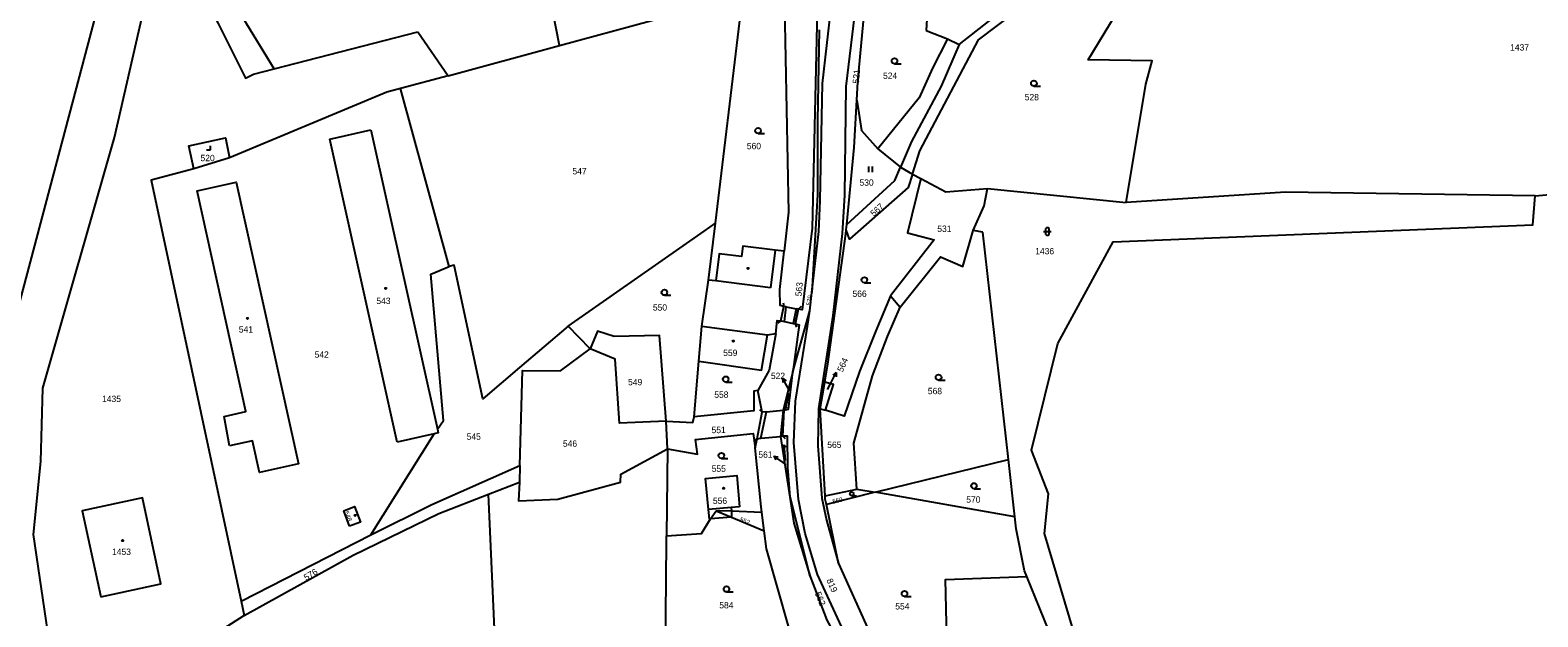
# Model space of a CAD drawing. Extents: x -520431 to -517205, y -1075927 to -1074013.
# Drawn here: x -518119.2 to -517715.9, y -1075681.5 to -1075524.8 of the extents above; entities that cross this region are included whole.
import ezdxf

# ---------------------------------------------------------------- set-up
doc = ezdxf.new("R2010")
doc.units = 0
for name, color, linetype in [('Hranice parcel', 7, 'Continuous'), ('Parcelní čísla', 7, 'Continuous'), ('Pop  PČ popisy', 7, 'Continuous'), ('Vnitřní kresba', 7, 'Continuous'), ('Značky budov', 7, 'Continuous'), ('Značky kultur', 7, 'Continuous')]:
    doc.layers.add(name, color=color, linetype=linetype)

msp = doc.modelspace()

# ---------------------------------------------------------------- linework, layer by layer
at = {"layer": 'Hranice parcel'}
for p, q in [((-517870.65, -1075528.6), (-517828.64, -1075495.46)), ((-517877.8, -1075495.74), (-517879.5, -1075524.81)), ((-517977.61, -1075528.88), (-517983.14, -1075499.93)), ((-517897.78, -1075538.57), (-517895.15, -1075510.36)), ((-517977.61, -1075528.88), (-517928.42, -1075515.49)), ((-518053.92, -1075535.11), (-518062.2, -1075521.51)), ((-517935.86, -1075576.31), (-517929.37, -1075522.17)), ((-518053.92, -1075535.11), (-518015.43, -1075525.22)), ((-518015.43, -1075525.22), (-518007.35, -1075536.98)), ((-517879.5, -1075524.81), (-517873.81, -1075527.06)), ((-517873.81, -1075527.06), (-517870.65, -1075528.6)), ((-518007.35, -1075536.98), (-517977.61, -1075528.88)), ((-518059.46, -1075536.53), (-518053.92, -1075535.11)), ((-518007.35, -1075536.98), (-518020.07, -1075540.33)), ((-517898.04, -1075543.43), (-517897.78, -1075538.57)), ((-518023.78, -1075541.31), (-518065.82, -1075558.88)), ((-518020.07, -1075540.33), (-518023.78, -1075541.31)), ((-518007.12, -1075587.89), (-518020.07, -1075540.33)), ((-518028.03, -1075551.41), (-518010.22, -1075631.43)), ((-518065.82, -1075558.88), (-518075.42, -1075561.82)), ((-517886.37, -1075561.4), (-517883.1, -1075563.22)), ((-517883.1, -1075563.22), (-517880.95, -1075564.42)), ((-517863.05, -1075567.09), (-517826.01, -1075570.84)), ((-517937.69, -1075591.53), (-517935.86, -1075576.31)), ((-517910.03, -1075594.89), (-517908.23, -1075578.54)), ((-517905.82, -1075614.05), (-517900.96, -1075579.19)), ((-517900.96, -1075579.19), (-517900.86, -1075578.16)), ((-517900.86, -1075578.16), (-517900.72, -1075576.71)), ((-517864.36, -1075578.76), (-517866.89, -1075578.28)), ((-517857.49, -1075639.51), (-517864.36, -1075578.76)), ((-517910.57, -1075599.74), (-517910.03, -1075594.89)), ((-517889.02, -1075595.73), (-517886.44, -1075598.8)), ((-517916.95, -1075598.69), (-517917.55, -1075598.58)), ((-517917.39, -1075602.63), (-517916.95, -1075598.69)), ((-517915.13, -1075616.09), (-517910.57, -1075599.74)), ((-517914.28, -1075599.21), (-517915.06, -1075603.11)), ((-517913.64, -1075599.33), (-517914.28, -1075599.21)), ((-517969.34, -1075609.95), (-517975.23, -1075603.83)), ((-517918.34, -1075602.44), (-517917.39, -1075602.63)), ((-517915.06, -1075603.11), (-517914.42, -1075603.24)), ((-517941.52, -1075628.09), (-517940.29, -1075613.25)), ((-517915.13, -1075616.09), (-517917.75, -1075626.3)), ((-517906.62, -1075618.8), (-517905.82, -1075614.05)), ((-517907.84, -1075625.92), (-517906.62, -1075618.8)), ((-517923.35, -1075626.86), (-517924.48, -1075621.04)), ((-517923.75, -1075633.75), (-517922.2, -1075626.75)), ((-517922.2, -1075626.75), (-517923.35, -1075626.86)), ((-517917.75, -1075626.3), (-517918.44, -1075633.31)), ((-517917.75, -1075626.3), (-517917.44, -1075626.27)), ((-517907.84, -1075625.92), (-517906.46, -1075626.34)), ((-517906.52, -1075649.19), (-517907.84, -1075625.92)), ((-518028.08, -1075659.64), (-518011.08, -1075632.65)), ((-518011.08, -1075632.65), (-518021.04, -1075634.9)), ((-517948.68, -1075636.65), (-517949.07, -1075629.21)), ((-517948.68, -1075636.65), (-517948.92, -1075659.87)), ((-517923.67, -1075652.14), (-517925.21, -1075636.42)), ((-517923.75, -1075633.75), (-517918.44, -1075633.31)), ((-517917.8, -1075633.25), (-517918.44, -1075633.31)), ((-517893.09, -1075648.23), (-517857.49, -1075639.51)), ((-517855.75, -1075654.84), (-517857.49, -1075639.51)), ((-517988.19, -1075641.07), (-517988.31, -1075645.53)), ((-517996.53, -1075648.79), (-517988.31, -1075645.53)), ((-517993.21, -1075725.03), (-517996.53, -1075648.79)), ((-517906.52, -1075649.19), (-517898.04, -1075647.38)), ((-517893.09, -1075648.23), (-517906.17, -1075651.54)), ((-517898.04, -1075647.38), (-517893.09, -1075648.23)), ((-517855.75, -1075654.84), (-517893.09, -1075648.23)), ((-517923.48, -1075653.64), (-517923.67, -1075652.14)), ((-517902.93, -1075667.29), (-517906.17, -1075651.54)), ((-517922.85, -1075658.53), (-517923.48, -1075653.64)), ((-517855.39, -1075658.03), (-517855.75, -1075654.84)), ((-518062.74, -1075677.38), (-518028.08, -1075659.64)), ((-517948.93, -1075661.56), (-517948.92, -1075659.87)), ((-517922.24, -1075663.35), (-517922.85, -1075658.53)), ((-517853.17, -1075669.24), (-517855.39, -1075658.03)), ((-517949.22, -1075695.82), (-517948.93, -1075661.56)), ((-517852.53, -1075670.8), (-517853.17, -1075669.24)), ((-517841.94, -1075696.76), (-517852.53, -1075670.8)), ((-518062.74, -1075677.38), (-518061.96, -1075681.23))]:
    msp.add_line(p, q, dxfattribs=at)
for points in [[(-517908.23, -1075578.54), (-517907.82, -1075570.25), (-517907.25, -1075539.04), (-517904.89, -1075518.73), (-517894.6, -1075467.56), (-517894.25, -1075463.86), (-517894.26, -1075460.26), (-517894.52, -1075452.87), (-517896.56, -1075433.9), (-517897.16, -1075426.01)], [(-517887.9, -1075457.19), (-517887.87, -1075460.35), (-517887.85, -1075462.57), (-517888.37, -1075468.59), (-517898.63, -1075520.7), (-517900.94, -1075539.84), (-517901.33, -1075568.86), (-517901.96, -1075579.13), (-517904.42, -1075601.03), (-517908.33, -1075625.84), (-517908.44, -1075635.83), (-517907.36, -1075649.79), (-517906.18, -1075655.68), (-517902.93, -1075667.29)], [(-518107.27, -1075709.57), (-518109.82, -1075693.22), (-518114.05, -1075688.54), (-518118.33, -1075659.57), (-518116.37, -1075640), (-518115.8, -1075620.46), (-518096.66, -1075553.44), (-518083.3, -1075495.38)], [(-518083.3, -1075495.38), (-518068.88, -1075522.94), (-518061.62, -1075537.56), (-518059.46, -1075536.53)], [(-517883.1, -1075563.22), (-517881.14, -1075557.03), (-517865.49, -1075527.34), (-517830.65, -1075500.93), (-517817.63, -1075493.15)], [(-518125.69, -1075721.88), (-518120.86, -1075706.74), (-518130.94, -1075649.23), (-518129.54, -1075625.65), (-518098.36, -1075508.57)], [(-517826.01, -1075570.84), (-517820.72, -1075539.22), (-517819, -1075532.99), (-517836.13, -1075532.69), (-517828.86, -1075520.67), (-517825.45, -1075508.41)], [(-517908.58, -1075515.54), (-517909.96, -1075577.65), (-517912.64, -1075599.49), (-517913.64, -1075599.33)], [(-517917.41, -1075518.48), (-517916.31, -1075573.36), (-517917.48, -1075583.83)], [(-517908.1, -1075524.7), (-517908.53, -1075549.01), (-517908.55, -1075568.78), (-517910.03, -1075594.89)], [(-517870.65, -1075528.6), (-517875.48, -1075539.71), (-517883.4, -1075554.48), (-517886.37, -1075561.4)], [(-517716.55, -1075569.07), (-517630.97, -1075561.31), (-517618.08, -1075550.38), (-517597.53, -1075535.05)], [(-517900.72, -1075576.71), (-517898.72, -1075556.11), (-517898.04, -1075543.43)], [(-517898.04, -1075543.43), (-517896.75, -1075551.54), (-517892.38, -1075556.45), (-517886.37, -1075561.4)], [(-518021.04, -1075634.9), (-518039.06, -1075553.91), (-518028.03, -1075551.41)], [(-518075.42, -1075561.82), (-518076.74, -1075555.66), (-518066.97, -1075553.51), (-518065.82, -1075558.88)], [(-518075.42, -1075561.82), (-518086.84, -1075564.87), (-518062.74, -1075677.38)], [(-517883.1, -1075563.22), (-517884.26, -1075566.8), (-517900.01, -1075580.61), (-517900.86, -1075578.16)], [(-517900.72, -1075576.71), (-517887.91, -1075564.97), (-517886.37, -1075561.4)], [(-518065.82, -1075635.81), (-518067.3, -1075627.99), (-518061.45, -1075626.7), (-518074.47, -1075567.68), (-518064.06, -1075565.34), (-518047.38, -1075640.64), (-518057.86, -1075642.96), (-518059.73, -1075634.47), (-518065.82, -1075635.81)], [(-517880.95, -1075564.42), (-517884.46, -1075578.96), (-517877.31, -1075580.76), (-517889.02, -1075595.73)], [(-517880.95, -1075564.42), (-517874.26, -1075567.99), (-517863.05, -1075567.09)], [(-517866.89, -1075578.28), (-517863.94, -1075571.66), (-517863.05, -1075567.09)], [(-517716.55, -1075569.07), (-517783.34, -1075568.02), (-517826.01, -1075570.84)], [(-517806.36, -1075723.7), (-517819.22, -1075715.13), (-517837.94, -1075692.54), (-517847.81, -1075659.24), (-517846.75, -1075648.71), (-517851.31, -1075636.96), (-517844.3, -1075608.48), (-517829.48, -1075581.32), (-517717.18, -1075576.77), (-517716.55, -1075569.07)], [(-517975.23, -1075603.83), (-517938.87, -1075578.49), (-517935.86, -1075576.31)], [(-517886.44, -1075598.8), (-517875.65, -1075585.3), (-517869.71, -1075587.89), (-517866.89, -1075578.28)], [(-517917.48, -1075583.83), (-517919.87, -1075583.54), (-517928.54, -1075582.47), (-517928.89, -1075585.27), (-517934.9, -1075584.54), (-517935.78, -1075591.76), (-517937.69, -1075591.53)], [(-517917.55, -1075598.58), (-517918.58, -1075598.32), (-517918.63, -1075594.02), (-517917.48, -1075583.83)], [(-518010.22, -1075631.43), (-518008.61, -1075629.06), (-518012.03, -1075589.98), (-518007.12, -1075587.89)], [(-517975.23, -1075603.83), (-517988.3, -1075614.95), (-517998.11, -1075623.27), (-518005.74, -1075587.57), (-518007.12, -1075587.89)], [(-517940.29, -1075613.25), (-517939.49, -1075603.84), (-517937.69, -1075591.53)], [(-517889.02, -1075595.73), (-517892.94, -1075605.07), (-517897.34, -1075616.02), (-517901.44, -1075627.88), (-517906.46, -1075626.34)], [(-517893.06, -1075703.93), (-517895.1, -1075699.24), (-517897.65, -1075693.7), (-517900.03, -1075688.77), (-517908.54, -1075670.21), (-517911.85, -1075659.26), (-517913.67, -1075650.22), (-517914.9, -1075634.97), (-517914.4, -1075623.91), (-517911.26, -1075603.96), (-517910.57, -1075599.74)], [(-517898.04, -1075647.38), (-517898.86, -1075635.1), (-517893.86, -1075617.11), (-517889.87, -1075606.66), (-517886.44, -1075598.8)], [(-517919.71, -1075605.79), (-517919.38, -1075602.32), (-517918.34, -1075602.44)], [(-517914.42, -1075603.24), (-517913.48, -1075603.52), (-517915.13, -1075616.09)], [(-517949.07, -1075629.21), (-517950.86, -1075606.4), (-517962.96, -1075606.59), (-517967.43, -1075605.2), (-517969.34, -1075609.95)], [(-517940.29, -1075613.25), (-517923.51, -1075615.6), (-517921.97, -1075606.18), (-517919.71, -1075605.79)], [(-517919.71, -1075605.79), (-517921.51, -1075615.62), (-517924.48, -1075621.04)], [(-517988.19, -1075641.07), (-517987.5, -1075615.72), (-517977.28, -1075615.8), (-517969.34, -1075609.95)], [(-517949.07, -1075629.21), (-517961.56, -1075629.77), (-517962.69, -1075612.65), (-517969.34, -1075609.95)], [(-517917.44, -1075626.27), (-517916.3, -1075626.06), (-517915.13, -1075616.09)], [(-517906.46, -1075626.34), (-517904.25, -1075619.42), (-517906.62, -1075618.8)], [(-517924.48, -1075621.04), (-517925.56, -1075621.25), (-517925.56, -1075626.51), (-517941.52, -1075628.09)], [(-517949.07, -1075629.21), (-517941.95, -1075629.65), (-517941.52, -1075628.09)], [(-518010.22, -1075631.43), (-518010, -1075632.41), (-518011.08, -1075632.65)], [(-517948.68, -1075636.65), (-517940.66, -1075638.09), (-517941.16, -1075634.17), (-517925.81, -1075632.57), (-517925.21, -1075636.42)], [(-517988.31, -1075645.53), (-517988.57, -1075650.56), (-517978, -1075650.14), (-517961.23, -1075645.55), (-517961.2, -1075643.42), (-517948.68, -1075636.65)], [(-517925.21, -1075636.42), (-517924.74, -1075633.99), (-517923.75, -1075633.75)], [(-517918.44, -1075633.31), (-517914.87, -1075656.49), (-517910.5, -1075670.78)], [(-517910.5, -1075670.78), (-517915.9, -1075649.51), (-517916.49, -1075641.59), (-517916.6, -1075633.27), (-517917.8, -1075633.25)], [(-518028.08, -1075659.64), (-518011.75, -1075651.48), (-517988.19, -1075641.07)], [(-517929.44, -1075652.16), (-517931.65, -1075652.36), (-517937.7, -1075652.89), (-517938.52, -1075644.57), (-517930.18, -1075643.81), (-517929.44, -1075652.16)], [(-518061.96, -1075681.23), (-518032.8, -1075665.09), (-518009.83, -1075653.95), (-517996.53, -1075648.79)], [(-518100.32, -1075676.22), (-518084.2, -1075672.69), (-518089.16, -1075649.7), (-518105.3, -1075653.18), (-518100.32, -1075676.22)], [(-518033.78, -1075657.29), (-518035.28, -1075653.19), (-518032.38, -1075652.09), (-518030.85, -1075656.21), (-518033.78, -1075657.29)], [(-517906.17, -1075651.54), (-517906.47, -1075650.06), (-517906.52, -1075649.19)], [(-517948.92, -1075659.87), (-517939.59, -1075659.29), (-517937.16, -1075655.38), (-517935.65, -1075653.19)], [(-517935.65, -1075653.19), (-517931.53, -1075654.95), (-517922.85, -1075658.53)], [(-517923.48, -1075653.64), (-517931.6, -1075653.34), (-517935.65, -1075653.19)], [(-517915.44, -1075686.85), (-517916.32, -1075684.08), (-517922.24, -1075663.35)], [(-517902.93, -1075667.29), (-517894.81, -1075685.27), (-517889.37, -1075696.64), (-517884.79, -1075710.63)], [(-517910.5, -1075670.78), (-517906.1, -1075682.41), (-517902.27, -1075689.29)], [(-517863.8, -1075732.34), (-517873.73, -1075698.85), (-517874.32, -1075671.54), (-517852.53, -1075670.8)], [(-518061.96, -1075681.23), (-518069.84, -1075686.25), (-518090.4, -1075701.07), (-518099.28, -1075708.75), (-518088.14, -1075746.39)]]:
    msp.add_lwpolyline(points, dxfattribs=at)
at = {"layer": 'Pop  PČ popisy'}
for p, q in [((-517904.93, -1075618.95), (-517903.57, -1075616.28)), ((-517903.57, -1075616.28), (-517904.47, -1075616.94)), ((-517903.57, -1075616.28), (-517903.58, -1075617.4)), ((-517916.42, -1075620.42), (-517917.88, -1075617.79)), ((-517917.88, -1075617.79), (-517916.95, -1075618.43)), ((-517917.88, -1075617.79), (-517917.83, -1075618.91)), ((-517916.01, -1075621.18), (-517916.42, -1075620.42)), ((-517905.88, -1075620.82), (-517904.93, -1075618.95)), ((-517917.76, -1075640.33), (-517920.22, -1075638.61)), ((-517920.22, -1075638.61), (-517919.11, -1075638.77)), ((-517920.22, -1075638.61), (-517919.68, -1075639.59)), ((-517916.91, -1075640.93), (-517917.76, -1075640.33))]:
    msp.add_line(p, q, dxfattribs=at)
at = {"layer": 'Vnitřní kresba'}
for p, q in [((-517873.81, -1075527.06), (-517877.75, -1075534.89)), ((-517877.75, -1075534.89), (-517881.33, -1075542.87)), ((-517881.33, -1075542.87), (-517892.38, -1075556.45)), ((-517919.87, -1075583.54), (-517921.09, -1075593.58)), ((-517921.09, -1075593.58), (-517935.78, -1075591.76)), ((-517918.34, -1075602.44), (-517917.55, -1075598.58)), ((-517917.71, -1075597.59), (-517917.55, -1075598.58)), ((-517916.95, -1075598.69), (-517914.28, -1075599.21)), ((-517914.42, -1075603.24), (-517913.64, -1075599.33)), ((-517912.92, -1075598.64), (-517913.64, -1075599.33)), ((-517939.49, -1075603.84), (-517921.97, -1075606.18)), ((-517919.1, -1075603.1), (-517918.34, -1075602.44)), ((-517917.39, -1075602.63), (-517915.06, -1075603.11)), ((-517914.06, -1075604.17), (-517914.42, -1075603.24)), ((-517924.74, -1075633.99), (-517923.35, -1075626.86)), ((-517924.03, -1075626.13), (-517923.35, -1075626.86)), ((-517922.2, -1075626.75), (-517917.75, -1075626.3)), ((-517917.8, -1075633.25), (-517917.44, -1075626.27)), ((-517916.78, -1075625.52), (-517917.44, -1075626.27)), ((-517925.6, -1075634.51), (-517924.74, -1075633.99)), ((-517917.08, -1075633.95), (-517917.8, -1075633.25)), ((-517931.65, -1075652.36), (-517931.6, -1075653.34)), ((-517937.45, -1075655.4), (-517937.7, -1075652.89)), ((-517937.16, -1075655.38), (-517937.45, -1075655.4)), ((-517931.53, -1075654.95), (-517937.16, -1075655.38)), ((-517931.6, -1075653.34), (-517931.53, -1075654.95))]:
    msp.add_line(p, q, dxfattribs=at)
at = {"layer": 'Značky budov'}
for centre in [(-517927.12, -1075588.43), (-518024.05, -1075593.76), (-518061.04, -1075601.79), (-517931.09, -1075607.85), (-517933.67, -1075647.18), (-518032.24, -1075654.43), (-518094.44, -1075661.16)]:
    msp.add_circle(centre, 0.175, dxfattribs=at)
at = {"layer": 'Značky kultur'}
for p, q in [((-517887.96, -1075533.76), (-517886.21, -1075533.76)), ((-517850.67, -1075539.73), (-517848.92, -1075539.73)), ((-518070.97, -1075556.7), (-518070.97, -1075555.7)), ((-517924.46, -1075552.38), (-517922.71, -1075552.38)), ((-518071.97, -1075556.7), (-518070.97, -1075556.7)), ((-517894.82, -1075562.67), (-517894.82, -1075561.17)), ((-517893.82, -1075562.67), (-517893.82, -1075561.17)), ((-517848.06, -1075578.56), (-517846.06, -1075578.56)), ((-517847.56, -1075578.06), (-517847.56, -1075579.06)), ((-517846.56, -1075579.06), (-517846.56, -1075578.06)), ((-517896.01, -1075592.26), (-517894.26, -1075592.26)), ((-517949.51, -1075595.6), (-517947.76, -1075595.6)), ((-517933.11, -1075618.79), (-517931.36, -1075618.79)), ((-517876.18, -1075618.29), (-517874.43, -1075618.29)), ((-517917.12, -1075625.96), (-517916.1, -1075621.88)), ((-517916.1, -1075621.88), (-517916.61, -1075622.46)), ((-517916.1, -1075621.88), (-517915.93, -1075622.63)), ((-517917.47, -1075635.55), (-517917.76, -1075636.26)), ((-517917.1, -1075639.73), (-517917.47, -1075635.55)), ((-517917.47, -1075635.55), (-517917.06, -1075636.2)), ((-517934.27, -1075639.21), (-517932.52, -1075639.21)), ((-517866.69, -1075647.3), (-517864.94, -1075647.3)), ((-517899.38, -1075649.2), (-517898.15, -1075649.2)), ((-517932.9, -1075674.88), (-517931.15, -1075674.88)), ((-517885.29, -1075676.08), (-517883.54, -1075676.08))]:
    msp.add_line(p, q, dxfattribs=at)
for centre, radius in [((-517887.96, -1075533.01), 0.75), ((-517850.67, -1075538.98), 0.75), ((-517924.46, -1075551.63), 0.75), ((-517896.01, -1075591.51), 0.75), ((-517949.51, -1075594.85), 0.75), ((-517933.11, -1075618.04), 0.75), ((-517876.18, -1075617.54), 0.75), ((-517934.27, -1075638.46), 0.75), ((-517899.38, -1075648.67), 0.525), ((-517866.69, -1075646.55), 0.75), ((-517932.9, -1075674.13), 0.75), ((-517885.29, -1075675.33), 0.75)]:
    msp.add_circle(centre, radius, dxfattribs=at)
for centre, start, end in [((-517847.06, -1075578.06), 0, 180), ((-517847.06, -1075579.06), 180, 359.9879)]:
    msp.add_arc(centre, 0.5, start, end, dxfattribs=at)

# ---------------------------------------------------------------- texts
at = {"layer": 'Parcelní čísla'}
for s, p in [('1437', (-517723.27, -1075530.2)), ('524', (-517891.03, -1075537.78)), ('528', (-517853.12, -1075543.51)), ('560', (-517927.46, -1075556.57)), ('520', (-518073.61, -1075559.77)), ('547', (-517974.11, -1075563.3)), ('530', (-517897.33, -1075566.34)), ('531', (-517876.52, -1075578.67)), ('1436', (-517850.32, -1075584.66)), ('543', (-518026.57, -1075597.94)), ('566', (-517899.2, -1075596.04)), ('550', (-517952.59, -1075599.7)), ('541', (-518063.36, -1075605.57)), ('542', (-518043.09, -1075612.3)), ('559', (-517933.79, -1075611.83)), ('522', (-517921.02, -1075617.99)), ('549', (-517959.23, -1075619.66)), ('568', (-517879.04, -1075622.04)), ('1435', (-518099.95, -1075624.14)), ('558', (-517936.17, -1075623.01)), ('545', (-518002.41, -1075634.22)), ('551', (-517936.9, -1075632.45)), ('546', (-517976.66, -1075636.1)), ('565', (-517905.95, -1075636.41)), ('561', (-517924.38, -1075639.04)), ('555', (-517936.86, -1075642.79)), ('556', (-517936.54, -1075651.37)), ('570', (-517868.76, -1075651.05)), ('1453', (-518097.28, -1075665)), ('584', (-517934.83, -1075679.28)), ('554', (-517887.76, -1075679.58))]:
    msp.add_text(s, height=1.7, dxfattribs=at).set_placement(p)
for s, height, rotation, p in [('521', 1.7, 85, (-517897.48, -1075539.08)), ('567', 1.7, 42, (-517893.49, -1075574.67)), ('563', 1.7, 84, (-517912.85, -1075595.97)), ('529', 1.2, 81, (-517910.39, -1075598.44)), ('564', 1.7, 66, (-517901.84, -1075616.27)), ('569', 1.2, 14, (-517904.39, -1075651.35)), ('548', 1.2, 292, (-518035.17, -1075653.6)), ('552', 1.2, 340, (-517929.47, -1075656)), ('576', 1.7, 31, (-518045.34, -1075671.93)), ('819', 1.7, 294, (-517906.2, -1075671.74)), ('562', 1.7, 292, (-517909.32, -1075675.25))]:
    msp.add_text(s, height=height, rotation=rotation, dxfattribs=at).set_placement(p)

doc.saveas('drawing.dxf')
